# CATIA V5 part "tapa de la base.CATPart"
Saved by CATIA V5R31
Part number: tapa de la base
Bounding box of the stored display mesh (mm): x -124.2 to 124.2, y -74.881 to 78.18, z 0 to 3.3
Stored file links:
  C:\Users\189361\Desktop\tapa de la base.CATPart
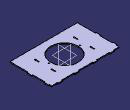
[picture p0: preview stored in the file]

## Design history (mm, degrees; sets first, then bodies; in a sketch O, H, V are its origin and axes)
Set1 "sketch"
  Sketch1 on xy-plane, origin (0, 0, 0), H (1, 0, 0), V (0, 1, 0)
    point P1 (-120.9, 74.8805)
    line L1 (-120.9, 74.8805) -> (-101.4847, 74.8805)
    point P2 (120.9, 74.8805)
    line L2 (120.9, 74.8805) -> (120.9, 66.0805)
    point P3 (120.9, -74.8805)
    line L3 (120.9, -74.8805) -> (-120.9, -74.8805)
    line L4 (-120.9, -74.8805) -> (-120.9, -9.7195)
    point P5 (-120.9, 66.0805)
    line L5 (-120.9, 66.0805) -> (-124.2, 66.0805)
    point P6 (-124.2, 66.0805)
    line L6 (-124.2, 66.0805) -> (-124.2, 50.2805)
    point P7 (-124.2, 50.2805)
    line L7 (-124.2, 50.2805) -> (-120.9, 50.2805)
    point P8 (-120.9, 50.2805)
    construction line L8 (-174.1544, 58.1805) -> (-110.566, 58.1805)
    construction line L9 (-134.4612, 50.6805) -> (-134.4612, 65.6805)
    point P11 (-134.4612, 50.6805)
    point P12 (-134.4612, 65.6805)
    line L10 (-120.9, 66.0805) -> (-120.9, 74.8805)
    construction line L11 (-186.0668, 28.1805) -> (-126.3564, 28.1805)
    point P15 (-120.9, 6.0805)
    point P16 (-124.2, 6.0805)
    line L12 (-124.2, 6.0805) -> (-120.9, 6.0805)
    point P17 (-124.2, -9.7195)
    line L13 (-124.2, -9.7195) -> (-124.2, 6.0805)
    point P18 (-120.9, -9.7195)
    line L14 (-120.9, -9.7195) -> (-124.2, -9.7195)
    line L15 (-120.9, 6.0805) -> (-120.9, 50.2805)
    point P19 (120.9, 66.0805)
    point P20 (124.2, 66.0805)
    point P21 (124.2, 50.2805)
    point P22 (120.9, 50.2805)
    point P23 (134.4612, 65.6805)
    point P24 (134.4612, 50.6805)
    construction line L16 (134.4612, 50.6805) -> (134.4612, 65.6805)
    point P25 (120.9, 6.0805)
    point P26 (124.2, 6.0805)
    point P27 (124.2, -9.7195)
    point P28 (120.9, -9.7195)
    line L17 (120.9, 66.0805) -> (124.2, 66.0805)
    line L18 (124.2, 66.0805) -> (124.2, 50.2805)
    line L19 (124.2, 50.2805) -> (120.9, 50.2805)
    line L20 (124.2, 6.0805) -> (120.9, 6.0805)
    line L21 (124.2, -9.7195) -> (124.2, 6.0805)
    line L22 (120.9, -9.7195) -> (124.2, -9.7195)
    line L23 (120.9, 6.0805) -> (120.9, 50.2805)
    line L24 (120.9, -9.7195) -> (120.9, -74.8805)
    point P29 (-101.4847, 74.8805)
    line L25 (-101.4847, 74.8805) -> (-101.4847, 78.1805)
    point P30 (-101.4847, 78.1805)
    line L26 (-101.4847, 78.1805) -> (-85.7198, 78.1805)
    point P31 (-85.7198, 78.1805)
    line L27 (-85.7198, 78.1805) -> (-85.7198, 74.8805)
    point P32 (-85.7198, 74.8805)
    construction line L28 (-93.4, 95.2872) -> (-93.4, 105.0953)
    construction line L29 (-101.0847, 99.534) -> (-86.1198, 99.534)
    point P35 (-101.0847, 99.534)
    point P36 (-86.1198, 99.534)
    construction line L30 (-63.4, 112.2198) -> (-63.4, 94.8044)
    line L31 (-85.7198, 74.8805) -> (-41.0802, 74.8805)
    point P39 (-25.3153, 78.1805)
    point P40 (-25.3153, 74.8805)
    line L32 (-25.3153, 74.8805) -> (-25.3153, 78.1805)
    point P41 (-41.0802, 78.1805)
    line L33 (-25.3153, 78.1805) -> (-41.0802, 78.1805)
    point P42 (-41.0802, 74.8805)
    line L34 (-41.0802, 78.1805) -> (-41.0802, 74.8805)
    line L35 (-25.3153, 74.8805) -> (25.3153, 74.8805)
    point P43 (25.3153, 78.1805)
    point P44 (25.3153, 74.8805)
    line L36 (25.3153, 74.8805) -> (25.3153, 78.1805)
    point P45 (41.0802, 78.1805)
    line L37 (25.3153, 78.1805) -> (41.0802, 78.1805)
    point P46 (41.0802, 74.8805)
    line L38 (41.0802, 78.1805) -> (41.0802, 74.8805)
    point P47 (85.7198, 74.8805)
    point P48 (85.7198, 78.1805)
    line L39 (85.7198, 78.1805) -> (85.7198, 74.8805)
    point P49 (101.4847, 78.1805)
    line L40 (101.4847, 78.1805) -> (85.7198, 78.1805)
    point P50 (101.4847, 74.8805)
    line L41 (101.4847, 74.8805) -> (101.4847, 78.1805)
    line L42 (41.0802, 74.8805) -> (85.7198, 74.8805)
    line L43 (101.4847, 74.8805) -> (120.9, 74.8805)
    circle A1 centre (0, 0) radius 50
    circle A2 centre (56, 0) radius 2.25
    point P51 (56, 0)
    circle A3 centre (-56, 0) radius 2.25
    point P53 (68.25, 22.5)
    line L44 (68.25, 22.5) -> (68.25, 37.5)
    point P54 (68.25, 37.5)
    line L45 (68.25, 37.5) -> (71.55, 37.5)
    point P55 (71.55, 37.5)
    line L46 (71.55, 37.5) -> (71.55, 22.5)
    point P56 (71.55, 22.5)
    line L47 (71.55, 22.5) -> (68.25, 22.5)
    point P57 (-68.25, 37.5)
    point P58 (-68.25, 22.5)
    line L48 (-68.25, 22.5) -> (-68.25, 37.5)
    point P59 (-71.55, 22.5)
    point P60 (-71.55, 37.5)
    line L49 (-71.55, 37.5) -> (-71.55, 22.5)
    line L50 (-71.55, 22.5) -> (-68.25, 22.5)
    line L51 (-68.25, 37.5) -> (-71.55, 37.5)
    axis line L52 (27.8269, 30) -> (50.2104, 30)
    point P63 (68.25, -22.5)
    point P64 (71.55, -22.5)
    line L53 (71.55, -22.5) -> (68.25, -22.5)
    point P65 (68.25, -37.5)
    line L54 (68.25, -22.5) -> (68.25, -37.5)
    point P66 (71.55, -37.5)
    line L55 (68.25, -37.5) -> (71.55, -37.5)
    line L56 (71.55, -37.5) -> (71.55, -22.5)
    point P67 (-68.25, -37.5)
    point P68 (-68.25, -22.5)
    line L57 (-68.25, -22.5) -> (-68.25, -37.5)
    point P69 (-71.55, -22.5)
    point P70 (-71.55, -37.5)
    line L58 (-71.55, -37.5) -> (-71.55, -22.5)
    line L59 (-71.55, -22.5) -> (-68.25, -22.5)
    line L60 (-68.25, -37.5) -> (-71.55, -37.5)
    distance H L1 = 74.8805
    length L5 = 3.3
    distance L8 L1 = 16.7
    length L9 = 15
    distance P12 L8 = 7.5
    distance L5 P12 = 0.4
    distance L7 P11 = 0.4
    distance L8 L11 = 30
    distance P2 P3 = 149.761
    length L29 = 14.9649
    distance P35 L28 = 7.6847
    distance L10 L28 = 27.5
    length L25 = 3.3
    distance L25 P35 = 0.4
    distance L27 P36 = 0.4
    distance L30 L28 = 30
    distance P1 P2 = 241.8
    radius A1 = 50
    radius A2 = 2.25
    distance P51 V = 56
    length L45 = 3.3
    length L46 = 15
    distance L44 A2 = 10
    distance L52 H = 30
    distance L52 L45 = 7.5
    horizontal: L1 H, L3 H, L5 H, L7 H, L8 H, L11 H, L26 H, L29 H, L31 H, L35 H, L42 H, L43 H, L45 H, L47 H, L52 H
    vertical: L2 V, L4 V, L6 V, L9 V, L10 V, L15 V, L24 V, L25 V, L27 V, L28 V, L30 V, L44 V, L46 V
    coincidence: P5 L4, L4 L10, L4 L15, P32 L1, L1 L31, L31 L35, L35 L42, L42 L43, P51 H
    symmetry: P8 P15 L11, P7 P16 L11, L7 L12 L11, P6 P17 L11, L6 L13 L11, P5 P18 L11, L5 L14 L11, P5 P19 V, P6 P20 V, P7 P21 V, P8 P22 V, P12 P23 V, P11 P24 V, L9 L16 V, P15 P25 V, P16 P26 V, P17 P27 V, P18 P28 V, L5 L17 V, L6 L18 V, L7 L19 V, L12 L20 V, L13 L21 V, L14 L22 V, L15 L23 V, P30 P39 L30, P29 P40 L30, L25 L32 L30, P31 P41 L30, L26 L33 L30, P32 P42 L30, L27 L34 L30, P39 P43 V, P40 P44 V, L32 L36 V, P41 P45 V, L33 L37 V, P42 P46 V, L34 L38 V, P32 P47 V, P31 P48 V, L27 L39 V, P30 P49 V, L26 L40 V, P29 P50 V, L25 L41 V, A2 A3 V, P54 P57 V, P53 P58 V, L44 L48 V, P56 P59 V, P55 P60 V, L46 L49 V, L47 L50 V, L45 L51 V, P53 P63 H, P56 P64 H, L47 L53 H, P54 P65 H, L44 L54 H, P55 P66 H, L45 L55 H, L46 L56 H, P57 P67 H, P58 P68 H, L48 L57 H, P59 P69 H, P60 P70 H, L49 L58 H, L50 L59 H, L51 L60 H
Body1 (main body)
  Pad1: profile Sketch1, direction (0, 0, 1), length 3.3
